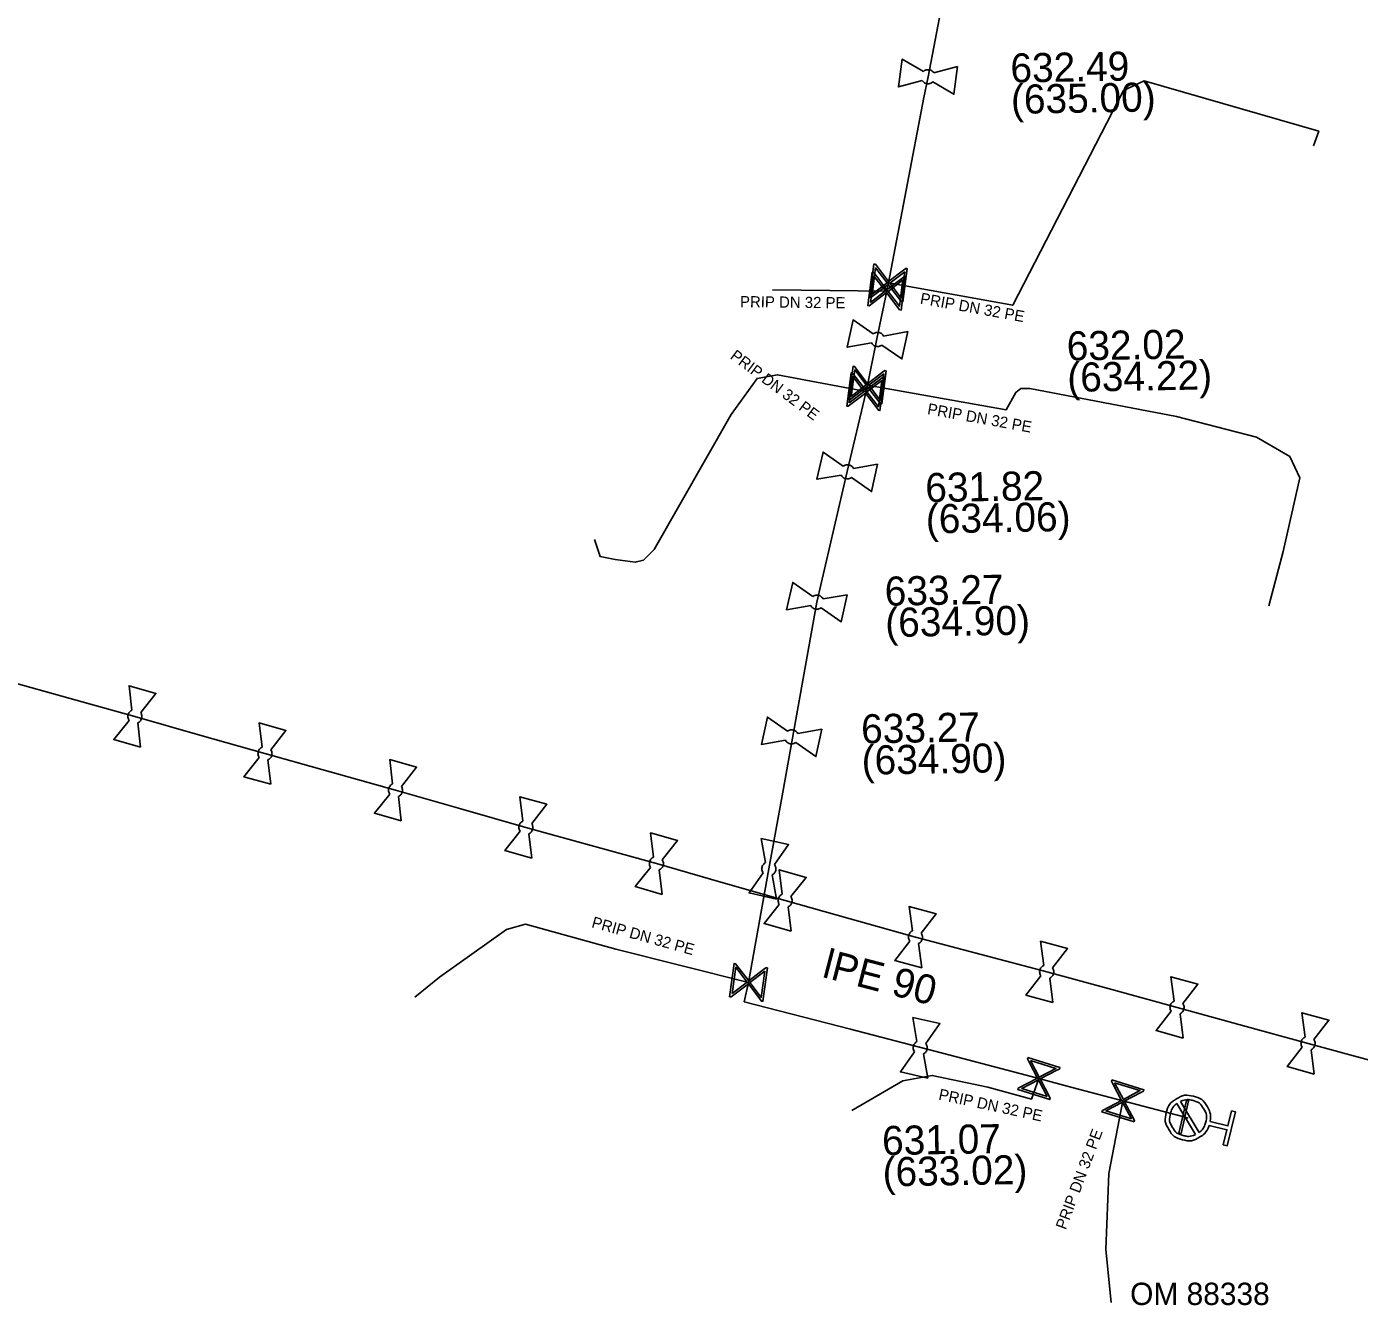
# Model space of a CAD drawing. Extents: x -638315 to -636370, y -1116147 to -1115110.
# Drawn here: x -637111.1 to -637051.5, y -1116140.5 to -1116083.4 of the extents above; entities that cross this region are included whole.
import ezdxf

# ---------------------------------------------------------------- set-up
doc = ezdxf.new("R2010")
doc.units = 0
for name, color, linetype in [('Default', 7, 'Continuous'), ('VP Hydrant', 7, 'Continuous'), ('VP Lomový bod', 7, 'Continuous'), ('VP Lomový bod - popis', 7, 'Continuous'), ('VP Popis nerozlišený', 7, 'Continuous'), ('VP Popis přípojky', 7, 'Continuous'), ('VP Přípojka', 7, 'Continuous'), ('VP Řad', 7, 'Continuous'), ('VP Řad - popis', 7, 'Continuous'), ('VP Šoupě', 7, 'Continuous')]:
    doc.layers.add(name, color=color, linetype=linetype)

msp = doc.modelspace()

# ---------------------------------------------------------------- linework, layer by layer
at = {"layer": 'Default'}
for points in [[(-637071.008, -1116085.367), (-637070.969, -1116085.331), (-637070.918, -1116085.311), (-637070.84, -1116085.279), (-637070.759, -1116085.29), (-637070.678, -1116085.301), (-637070.608, -1116085.353), (-637070.566, -1116085.385), (-637070.537, -1116085.429)], [(-637070.591, -1116085.835), (-637070.63, -1116085.869), (-637070.68, -1116085.889), (-637070.76, -1116085.921), (-637070.841, -1116085.91), (-637070.922, -1116085.899), (-637070.99, -1116085.848), (-637071.033, -1116085.815), (-637071.062, -1116085.771)], [(-637073.249, -1116097.1), (-637073.207, -1116097.067), (-637073.155, -1116097.051), (-637073.074, -1116097.026), (-637072.995, -1116097.043), (-637072.915, -1116097.06), (-637072.85, -1116097.118), (-637072.81, -1116097.153), (-637072.785, -1116097.199)], [(-637072.87, -1116097.599), (-637072.912, -1116097.63), (-637072.963, -1116097.647), (-637073.046, -1116097.671), (-637073.126, -1116097.654), (-637073.206, -1116097.637), (-637073.269, -1116097.581), (-637073.309, -1116097.545), (-637073.334, -1116097.498)], [(-637074.596, -1116103.016), (-637074.554, -1116102.984), (-637074.502, -1116102.968), (-637074.421, -1116102.944), (-637074.341, -1116102.962), (-637074.261, -1116102.979), (-637074.197, -1116103.038), (-637074.157, -1116103.073), (-637074.133, -1116103.12)], [(-637074.222, -1116103.519), (-637074.264, -1116103.549), (-637074.315, -1116103.565), (-637074.398, -1116103.589), (-637074.478, -1116103.571), (-637074.558, -1116103.554), (-637074.62, -1116103.497), (-637074.661, -1116103.46), (-637074.685, -1116103.414)], [(-637075.957, -1116108.849), (-637075.914, -1116108.817), (-637075.862, -1116108.802), (-637075.781, -1116108.777), (-637075.702, -1116108.795), (-637075.622, -1116108.813), (-637075.557, -1116108.871), (-637075.518, -1116108.906), (-637075.493, -1116108.953)], [(-637075.583, -1116109.352), (-637075.624, -1116109.383), (-637075.676, -1116109.399), (-637075.759, -1116109.423), (-637075.838, -1116109.405), (-637075.918, -1116109.387), (-637075.981, -1116109.331), (-637076.021, -1116109.294), (-637076.046, -1116109.247)], [(-637106.543, -1116114.383), (-637106.571, -1116114.339), (-637106.584, -1116114.287), (-637106.603, -1116114.203), (-637106.581, -1116114.124), (-637106.558, -1116114.046), (-637106.498, -1116113.987), (-637106.459, -1116113.948), (-637106.411, -1116113.926)], [(-637106.019, -1116114.038), (-637105.99, -1116114.082), (-637105.977, -1116114.135), (-637105.957, -1116114.217), (-637105.979, -1116114.296), (-637106.002, -1116114.374), (-637106.064, -1116114.435), (-637106.101, -1116114.473), (-637106.149, -1116114.495)], [(-637077.087, -1116114.871), (-637077.044, -1116114.839), (-637076.992, -1116114.824), (-637076.911, -1116114.799), (-637076.832, -1116114.817), (-637076.752, -1116114.835), (-637076.687, -1116114.893), (-637076.648, -1116114.928), (-637076.623, -1116114.975)], [(-637100.722, -1116116.044), (-637100.75, -1116116), (-637100.763, -1116115.948), (-637100.783, -1116115.864), (-637100.761, -1116115.786), (-637100.739, -1116115.707), (-637100.679, -1116115.647), (-637100.64, -1116115.609), (-637100.592, -1116115.587)], [(-637100.2, -1116115.697), (-637100.17, -1116115.741), (-637100.157, -1116115.794), (-637100.137, -1116115.876), (-637100.159, -1116115.954), (-637100.181, -1116116.033), (-637100.243, -1116116.095), (-637100.28, -1116116.132), (-637100.328, -1116116.154)], [(-637076.713, -1116115.374), (-637076.754, -1116115.405), (-637076.806, -1116115.421), (-637076.889, -1116115.445), (-637076.968, -1116115.427), (-637077.048, -1116115.409), (-637077.111, -1116115.353), (-637077.151, -1116115.316), (-637077.176, -1116115.269)], [(-637094.882, -1116117.683), (-637094.911, -1116117.639), (-637094.924, -1116117.587), (-637094.943, -1116117.503), (-637094.921, -1116117.424), (-637094.898, -1116117.346), (-637094.838, -1116117.287), (-637094.799, -1116117.248), (-637094.751, -1116117.226)], [(-637094.359, -1116117.338), (-637094.33, -1116117.382), (-637094.317, -1116117.435), (-637094.297, -1116117.517), (-637094.319, -1116117.596), (-637094.342, -1116117.674), (-637094.404, -1116117.735), (-637094.441, -1116117.773), (-637094.489, -1116117.795)], [(-637089.051, -1116119.345), (-637089.08, -1116119.301), (-637089.093, -1116119.249), (-637089.113, -1116119.165), (-637089.091, -1116119.086), (-637089.069, -1116119.008), (-637089.01, -1116118.948), (-637088.971, -1116118.909), (-637088.923, -1116118.887)], [(-637088.53, -1116118.996), (-637088.501, -1116119.04), (-637088.487, -1116119.093), (-637088.467, -1116119.175), (-637088.489, -1116119.254), (-637088.511, -1116119.332), (-637088.572, -1116119.394), (-637088.609, -1116119.432), (-637088.657, -1116119.454)], [(-637083.213, -1116120.962), (-637083.241, -1116120.919), (-637083.254, -1116120.867), (-637083.273, -1116120.783), (-637083.25, -1116120.704), (-637083.228, -1116120.625), (-637083.168, -1116120.566), (-637083.129, -1116120.528), (-637083.081, -1116120.506)], [(-637082.689, -1116120.618), (-637082.659, -1116120.662), (-637082.647, -1116120.716), (-637082.627, -1116120.797), (-637082.65, -1116120.876), (-637082.672, -1116120.955), (-637082.734, -1116121.016), (-637082.771, -1116121.053), (-637082.82, -1116121.075)], [(-637078.171, -1116121.207), (-637078.203, -1116121.164), (-637078.218, -1116121.112), (-637078.243, -1116121.031), (-637078.225, -1116120.952), (-637078.207, -1116120.872), (-637078.149, -1116120.807), (-637078.114, -1116120.768), (-637078.067, -1116120.743)], [(-637077.668, -1116120.833), (-637077.637, -1116120.874), (-637077.621, -1116120.926), (-637077.597, -1116121.009), (-637077.615, -1116121.088), (-637077.633, -1116121.168), (-637077.689, -1116121.231), (-637077.726, -1116121.271), (-637077.773, -1116121.296)], [(-637077.452, -1116122.614), (-637077.48, -1116122.57), (-637077.494, -1116122.518), (-637077.513, -1116122.434), (-637077.491, -1116122.355), (-637077.469, -1116122.277), (-637077.409, -1116122.217), (-637077.37, -1116122.179), (-637077.322, -1116122.157)], [(-637076.93, -1116122.267), (-637076.9, -1116122.311), (-637076.887, -1116122.364), (-637076.867, -1116122.446), (-637076.889, -1116122.525), (-637076.911, -1116122.603), (-637076.973, -1116122.665), (-637077.01, -1116122.702), (-637077.058, -1116122.724)], [(-637071.619, -1116124.258), (-637071.648, -1116124.215), (-637071.662, -1116124.163), (-637071.683, -1116124.079), (-637071.662, -1116124), (-637071.641, -1116123.921), (-637071.582, -1116123.861), (-637071.544, -1116123.822), (-637071.497, -1116123.799)], [(-637071.102, -1116123.903), (-637071.072, -1116123.946), (-637071.058, -1116123.999), (-637071.037, -1116124.081), (-637071.058, -1116124.16), (-637071.079, -1116124.239), (-637071.139, -1116124.301), (-637071.176, -1116124.339), (-637071.224, -1116124.362)], [(-637065.75, -1116125.806), (-637065.779, -1116125.762), (-637065.793, -1116125.711), (-637065.813, -1116125.627), (-637065.791, -1116125.548), (-637065.77, -1116125.469), (-637065.711, -1116125.409), (-637065.672, -1116125.37), (-637065.624, -1116125.348)], [(-637065.231, -1116125.455), (-637065.201, -1116125.499), (-637065.188, -1116125.552), (-637065.167, -1116125.633), (-637065.189, -1116125.712), (-637065.21, -1116125.791), (-637065.271, -1116125.853), (-637065.308, -1116125.891), (-637065.356, -1116125.913)], [(-637059.921, -1116127.395), (-637059.949, -1116127.352), (-637059.963, -1116127.3), (-637059.983, -1116127.216), (-637059.961, -1116127.137), (-637059.94, -1116127.058), (-637059.88, -1116126.999), (-637059.842, -1116126.96), (-637059.794, -1116126.938)], [(-637059.401, -1116127.046), (-637059.371, -1116127.089), (-637059.358, -1116127.142), (-637059.337, -1116127.224), (-637059.359, -1116127.303), (-637059.38, -1116127.382), (-637059.442, -1116127.443), (-637059.479, -1116127.481), (-637059.526, -1116127.504)], [(-637071.4, -1116129.212), (-637071.432, -1116129.169), (-637071.448, -1116129.117), (-637071.472, -1116129.036), (-637071.454, -1116128.957), (-637071.437, -1116128.877), (-637071.378, -1116128.812), (-637071.343, -1116128.773), (-637071.296, -1116128.748)], [(-637070.897, -1116128.838), (-637070.867, -1116128.879), (-637070.851, -1116128.931), (-637070.827, -1116129.014), (-637070.845, -1116129.093), (-637070.862, -1116129.173), (-637070.919, -1116129.236), (-637070.956, -1116129.276), (-637071.002, -1116129.301)], [(-637054.061, -1116129.005), (-637054.089, -1116128.962), (-637054.103, -1116128.91), (-637054.123, -1116128.826), (-637054.101, -1116128.747), (-637054.08, -1116128.669), (-637054.02, -1116128.609), (-637053.982, -1116128.57), (-637053.934, -1116128.548)], [(-637053.541, -1116128.655), (-637053.511, -1116128.699), (-637053.498, -1116128.752), (-637053.477, -1116128.834), (-637053.499, -1116128.913), (-637053.52, -1116128.991), (-637053.581, -1116129.053), (-637053.618, -1116129.091), (-637053.666, -1116129.113)], [(-637058.224, -1116132.497), (-637058.339, -1116132.839), (-637058.654, -1116133.026), (-637059.008, -1116133.238), (-637059.412, -1116133.138), (-637059.814, -1116133.038), (-637060.027, -1116132.684), (-637060.239, -1116132.329), (-637060.139, -1116131.925), (-637060.04, -1116131.525), (-637059.686, -1116131.311), (-637059.332, -1116131.097), (-637058.93, -1116131.197), (-637058.526, -1116131.297), (-637058.312, -1116131.65), (-637058.12, -1116131.964), (-637058.18, -1116132.319)], [(-637059.665, -1116131.522), (-637059.886, -1116131.69), (-637059.955, -1116131.971), (-637060.036, -1116132.297), (-637059.863, -1116132.585), (-637059.69, -1116132.874), (-637059.362, -1116132.955), (-637059.082, -1116133.025), (-637058.83, -1116132.908)], [(-637058.673, -1116132.814), (-637058.449, -1116132.647), (-637058.378, -1116132.362), (-637058.297, -1116132.034), (-637058.47, -1116131.747), (-637058.643, -1116131.459), (-637058.971, -1116131.378), (-637059.255, -1116131.307), (-637059.508, -1116131.428)]]:
    msp.add_open_spline(points, degree=3, dxfattribs=at)
at = {"layer": 'VP Hydrant'}
for points in [[(-637058.83, -1116132.908), (-637059.665, -1116131.522)], [(-637059.508, -1116131.428), (-637058.673, -1116132.814)], [(-637058.18, -1116132.319), (-637057.384, -1116132.517), (-637057.218, -1116131.848), (-637057.04, -1116131.892), (-637057.416, -1116133.408), (-637057.594, -1116133.364), (-637057.428, -1116132.695), (-637058.224, -1116132.497)]]:
    msp.add_lwpolyline(points, dxfattribs=at)
at = {"layer": 'VP Lomový bod'}
for points in [[(-637071.062, -1116085.771), (-637072.122, -1116086.054), (-637071.956, -1116084.815), (-637071.008, -1116085.367)], [(-637069.478, -1116085.146), (-637069.644, -1116086.385), (-637070.591, -1116085.835)], [(-637070.537, -1116085.429), (-637069.478, -1116085.146)], [(-637073.334, -1116097.498), (-637074.413, -1116097.697), (-637074.151, -1116096.475), (-637073.249, -1116097.1)], [(-637071.707, -1116097), (-637071.969, -1116098.222), (-637072.87, -1116097.599)], [(-637072.785, -1116097.199), (-637071.707, -1116097)], [(-637074.685, -1116103.414), (-637075.766, -1116103.603), (-637075.493, -1116102.383), (-637074.596, -1116103.016)], [(-637073.053, -1116102.93), (-637073.326, -1116104.15), (-637074.222, -1116103.519)], [(-637074.133, -1116103.12), (-637073.053, -1116102.93)], [(-637076.046, -1116109.247), (-637077.126, -1116109.437), (-637076.853, -1116108.217), (-637075.957, -1116108.849)], [(-637074.414, -1116108.763), (-637074.687, -1116109.983), (-637075.583, -1116109.352)], [(-637075.493, -1116108.953), (-637074.414, -1116108.763)], [(-637106.411, -1116113.926), (-637106.538, -1116112.837), (-637105.336, -1116113.179), (-637106.019, -1116114.038)], [(-637106.022, -1116115.583), (-637107.224, -1116115.241), (-637106.543, -1116114.383)], [(-637106.149, -1116114.495), (-637106.022, -1116115.583)], [(-637100.592, -1116115.587), (-637100.724, -1116114.498), (-637099.52, -1116114.836), (-637100.2, -1116115.697)], [(-637077.176, -1116115.269), (-637078.256, -1116115.459), (-637077.983, -1116114.239), (-637077.087, -1116114.871)], [(-637075.544, -1116114.785), (-637075.817, -1116116.005), (-637076.713, -1116115.374)], [(-637076.623, -1116114.975), (-637075.544, -1116114.785)], [(-637100.196, -1116117.242), (-637101.4, -1116116.904), (-637100.722, -1116116.044)], [(-637100.328, -1116116.154), (-637100.196, -1116117.242)], [(-637094.751, -1116117.226), (-637094.879, -1116116.137), (-637093.677, -1116116.479), (-637094.359, -1116117.338)], [(-637094.361, -1116118.883), (-637095.563, -1116118.541), (-637094.882, -1116117.683)], [(-637094.489, -1116117.795), (-637094.361, -1116118.883)], [(-637088.923, -1116118.887), (-637089.058, -1116117.798), (-637087.854, -1116118.133), (-637088.53, -1116118.996)], [(-637088.522, -1116120.542), (-637089.726, -1116120.207), (-637089.051, -1116119.345)], [(-637088.657, -1116119.454), (-637088.522, -1116120.542)], [(-637083.081, -1116120.506), (-637083.207, -1116119.416), (-637082.005, -1116119.76), (-637082.689, -1116120.618)], [(-637078.257, -1116119.664), (-637077.037, -1116119.937), (-637077.668, -1116120.833)], [(-637078.067, -1116120.743), (-637078.257, -1116119.664)], [(-637082.693, -1116122.164), (-637083.895, -1116121.82), (-637083.213, -1116120.962)], [(-637082.82, -1116121.075), (-637082.693, -1116122.164)], [(-637077.322, -1116122.157), (-637077.453, -1116121.067), (-637076.25, -1116121.406), (-637076.93, -1116122.267)], [(-637077.773, -1116121.296), (-637077.583, -1116122.376), (-637078.803, -1116122.103), (-637078.171, -1116121.207)], [(-637076.927, -1116123.813), (-637078.13, -1116123.474), (-637077.452, -1116122.614)], [(-637077.058, -1116122.724), (-637076.927, -1116123.813)], [(-637071.497, -1116123.799), (-637071.645, -1116122.712), (-637070.437, -1116123.031), (-637071.102, -1116123.903)], [(-637071.075, -1116125.448), (-637072.283, -1116125.129), (-637071.619, -1116124.258)], [(-637071.224, -1116124.362), (-637071.075, -1116125.448)], [(-637065.624, -1116125.348), (-637065.764, -1116124.26), (-637064.558, -1116124.588), (-637065.231, -1116125.455)], [(-637065.216, -1116127), (-637066.422, -1116126.672), (-637065.75, -1116125.806)], [(-637059.794, -1116126.938), (-637059.932, -1116125.849), (-637058.726, -1116126.18), (-637059.401, -1116127.046)], [(-637065.356, -1116125.913), (-637065.216, -1116127)], [(-637059.388, -1116128.591), (-637060.594, -1116128.26), (-637059.921, -1116127.395)], [(-637059.526, -1116127.504), (-637059.388, -1116128.591)], [(-637053.934, -1116128.548), (-637054.072, -1116127.459), (-637052.867, -1116127.79), (-637053.541, -1116128.655)], [(-637071.486, -1116127.669), (-637070.266, -1116127.942), (-637070.897, -1116128.838)], [(-637071.296, -1116128.748), (-637071.486, -1116127.669)], [(-637071.002, -1116129.301), (-637070.813, -1116130.381), (-637072.033, -1116130.108), (-637071.4, -1116129.212)], [(-637053.528, -1116130.201), (-637054.733, -1116129.87), (-637054.061, -1116129.005)], [(-637053.666, -1116129.113), (-637053.528, -1116130.201)]]:
    msp.add_lwpolyline(points, dxfattribs=at)
at = {"layer": 'VP Přípojka'}
for points in [[(-637072.574, -1116094.823), (-637067.009, -1116095.822), (-637062.05, -1116086.21), (-637061.13, -1116085.78), (-637053.32, -1116088.04), (-637053.556, -1116088.685)], [(-637077.76, -1116095.13), (-637072.649, -1116095.189)], [(-637085.721, -1116106.296), (-637085.47, -1116107.06), (-637084.8, -1116107.19), (-637083.9, -1116107.31), (-637083.53, -1116107.22), (-637083.05, -1116106.75), (-637079.6, -1116100.71), (-637078.45, -1116099.09), (-637077.54, -1116098.93), (-637073.57, -1116099.68)], [(-637073.51, -1116099.39), (-637067.31, -1116100.5), (-637066.87, -1116099.72), (-637066.65, -1116099.55), (-637066.45, -1116099.545), (-637066.25, -1116099.54), (-637059.68, -1116100.79), (-637056.1, -1116101.72), (-637054.61, -1116102.59), (-637054.16, -1116103.54), (-637054.91, -1116106.83), (-637055.56, -1116109.26)], [(-637093.76, -1116126.76), (-637092.65, -1116125.87), (-637089.66, -1116123.74), (-637088.81, -1116123.5), (-637084.77, -1116124.62), (-637078.83, -1116126.1)], [(-637074.21, -1116131.83), (-637071.93, -1116130.51), (-637070.61, -1116130.26), (-637068.13, -1116130.79), (-637066.17, -1116131.32), (-637065.841, -1116130.403)], [(-637062.08, -1116131.398), (-637062.71, -1116134.65), (-637062.84, -1116138.04), (-637062.6, -1116140.42)]]:
    msp.add_lwpolyline(points, dxfattribs=at)
at = {"layer": 'VP Řad'}
for points in [[(-637069.85, -1116080.67), (-637070.8, -1116085.6), (-637070.98, -1116086.53), (-637072.574, -1116094.823), (-637072.6, -1116094.95), (-637072.649, -1116095.189), (-637073.085, -1116097.315), (-637073.51, -1116099.39), (-637073.57, -1116099.68), (-637074.413, -1116103.254), (-637075.77, -1116109.1), (-637077.3, -1116117.6), (-637077.92, -1116121.02), (-637078.83, -1116126.1), (-637079.02, -1116126.97), (-637074.27, -1116128.2), (-637069.52, -1116129.43), (-637065.841, -1116130.403), (-637064.345, -1116130.799), (-637062.08, -1116131.398), (-637059.358, -1116132.118), (-637059.169, -1116132.168)], [(-637050.88, -1116129.63), (-637053.8, -1116128.83), (-637056.73, -1116128.025), (-637059.66, -1116127.22), (-637062.575, -1116126.425), (-637065.49, -1116125.63), (-637068.425, -1116124.855), (-637071.36, -1116124.08), (-637074.275, -1116123.26), (-637077.19, -1116122.44), (-637080.07, -1116121.615), (-637082.95, -1116120.79), (-637085.87, -1116119.98), (-637088.79, -1116119.17), (-637091.705, -1116118.34), (-637094.62, -1116117.51), (-637097.54, -1116116.69), (-637100.46, -1116115.87), (-637103.37, -1116115.04), (-637106.28, -1116114.21), (-637109.17, -1116113.405), (-637112.06, -1116112.6)]]:
    msp.add_lwpolyline(points, dxfattribs=at)
at = {"layer": 'VP Šoupě'}
for points in [[(-637071.73, -1116094.18), (-637071.931, -1116095.667), (-637071.996, -1116095.658), (-637072.071, -1116095.553), (-637072.581, -1116094.886), (-637073.352, -1116095.475), (-637073.418, -1116095.466), (-637073.217, -1116093.979), (-637073.152, -1116093.988), (-637072.564, -1116094.762), (-637071.897, -1116094.252), (-637071.796, -1116094.171), (-637071.73, -1116094.18)], [(-637073.304, -1116095.328), (-637072.634, -1116094.816), (-637073.145, -1116094.147), (-637073.304, -1116095.328)], [(-637071.805, -1116094.546), (-637072.006, -1116096.033), (-637072.071, -1116096.024), (-637072.146, -1116095.919), (-637072.656, -1116095.252), (-637073.427, -1116095.841), (-637073.493, -1116095.832), (-637073.292, -1116094.345), (-637073.227, -1116094.354), (-637072.639, -1116095.128), (-637071.972, -1116094.618), (-637071.871, -1116094.537), (-637071.805, -1116094.546)], [(-637073.379, -1116095.694), (-637072.709, -1116095.182), (-637073.22, -1116094.513), (-637073.379, -1116095.694)], [(-637071.919, -1116094.69), (-637072.586, -1116095.198), (-637072.078, -1116095.863), (-637071.919, -1116094.69)], [(-637071.844, -1116094.324), (-637072.511, -1116094.832), (-637072.003, -1116095.497), (-637071.844, -1116094.324)], [(-637072.75, -1116099.041), (-637072.951, -1116100.528), (-637073.016, -1116100.519), (-637073.091, -1116100.414), (-637073.601, -1116099.747), (-637074.372, -1116100.336), (-637074.437, -1116100.327), (-637074.237, -1116098.841), (-637074.171, -1116098.85), (-637073.584, -1116099.624), (-637072.917, -1116099.113), (-637072.815, -1116099.033), (-637072.75, -1116099.041)], [(-637072.666, -1116098.747), (-637072.867, -1116100.234), (-637072.932, -1116100.225), (-637073.007, -1116100.12), (-637073.517, -1116099.453), (-637074.288, -1116100.042), (-637074.354, -1116100.033), (-637074.153, -1116098.546), (-637074.088, -1116098.555), (-637073.5, -1116099.329), (-637072.833, -1116098.819), (-637072.732, -1116098.738), (-637072.666, -1116098.747)], [(-637074.324, -1116100.189), (-637073.654, -1116099.677), (-637074.165, -1116099.009), (-637074.324, -1116100.189)], [(-637074.24, -1116099.895), (-637073.57, -1116099.383), (-637074.081, -1116098.714), (-637074.24, -1116099.895)], [(-637072.78, -1116098.891), (-637073.447, -1116099.399), (-637072.939, -1116100.064), (-637072.78, -1116098.891)], [(-637072.864, -1116099.185), (-637073.531, -1116099.694), (-637073.022, -1116100.359), (-637072.864, -1116099.185)], [(-637077.986, -1116125.457), (-637078.187, -1116126.944), (-637078.252, -1116126.935), (-637078.327, -1116126.83), (-637078.837, -1116126.163), (-637079.608, -1116126.752), (-637079.674, -1116126.743), (-637079.473, -1116125.256), (-637079.408, -1116125.265), (-637078.82, -1116126.039), (-637078.153, -1116125.529), (-637078.052, -1116125.448), (-637077.986, -1116125.457)], [(-637079.56, -1116126.605), (-637078.89, -1116126.093), (-637079.401, -1116125.424), (-637079.56, -1116126.605)], [(-637078.1, -1116125.601), (-637078.767, -1116126.109), (-637078.259, -1116126.774), (-637078.1, -1116125.601)], [(-637066.33, -1116129.461), (-637064.9, -1116129.915), (-637064.92, -1116129.978), (-637065.036, -1116130.033), (-637065.781, -1116130.421), (-637065.333, -1116131.282), (-637065.353, -1116131.345), (-637066.783, -1116130.891), (-637066.763, -1116130.828), (-637065.9, -1116130.383), (-637066.287, -1116129.638), (-637066.349, -1116129.524), (-637066.33, -1116129.461)], [(-637066.208, -1116129.598), (-637065.821, -1116130.343), (-637065.079, -1116129.956), (-637066.208, -1116129.598)], [(-637065.47, -1116131.209), (-637065.859, -1116130.461), (-637066.605, -1116130.849), (-637065.47, -1116131.209)], [(-637062.578, -1116130.462), (-637061.144, -1116130.9), (-637061.163, -1116130.963), (-637061.278, -1116131.02), (-637062.019, -1116131.415), (-637061.563, -1116132.271), (-637061.582, -1116132.334), (-637063.017, -1116131.896), (-637062.997, -1116131.833), (-637062.139, -1116131.379), (-637062.534, -1116130.637), (-637062.598, -1116130.525), (-637062.578, -1116130.462)], [(-637062.455, -1116130.597), (-637062.061, -1116131.337), (-637061.322, -1116130.943), (-637062.455, -1116130.597)], [(-637061.7, -1116132.2), (-637062.097, -1116131.456), (-637062.839, -1116131.852), (-637061.7, -1116132.2)], [(-637059.573, -1116132.838), (-637059.234, -1116131.377), (-637059.143, -1116131.398), (-637059.482, -1116132.859), (-637059.573, -1116132.838)]]:
    msp.add_lwpolyline(points, dxfattribs=at)

# ---------------------------------------------------------------- texts
at = {"layer": 'VP Lomový bod - popis'}
for s, p in [('632.49', (-637067.103, -1116085.863)), ('(635.00)', (-637067.079, -1116087.263)), ('632.02', (-637064.584, -1116098.294)), ('(634.22)', (-637064.559, -1116099.694)), ('631.82', (-637070.911, -1116104.627)), ('(634.06)', (-637070.887, -1116106.027)), ('633.27', (-637072.727, -1116109.259)), ('(634.90)', (-637072.703, -1116110.659)), ('633.27', (-637073.782, -1116115.416)), ('(634.90)', (-637073.758, -1116116.816)), ('631.07', (-637072.845, -1116133.828)), ('(633.02)', (-637072.82, -1116135.228))]:
    msp.add_text(s, height=1.3, rotation=1, dxfattribs=at).set_placement(p)
at = {"layer": 'VP Popis nerozlišený'}
msp.add_text('OM 88338', height=1, dxfattribs=at).set_placement((-637061.758, -1116140.53))
at = {"layer": 'VP Popis přípojky'}
for rotation, p in [(359.33862, (-637079.213, -1116095.906)), (349.82563, (-637071.18, -1116095.745)), (323.19452, (-637079.685, -1116098.173)), (349.84974, (-637070.856, -1116100.688)), (344.50515, (-637085.88, -1116123.629)), (347.9368, (-637070.357, -1116131.338)), (69.39067, (-637064.638, -1116137.194))]:
    msp.add_text('PRIP DN 32 PE', height=0.5, rotation=rotation, dxfattribs=at).set_placement(p)
at = {"layer": 'VP Řad - popis'}
msp.add_text('lPE 90', height=1.3, rotation=345.48229, dxfattribs=at).set_placement((-637075.582, -1116125.854))

doc.saveas('drawing.dxf')
